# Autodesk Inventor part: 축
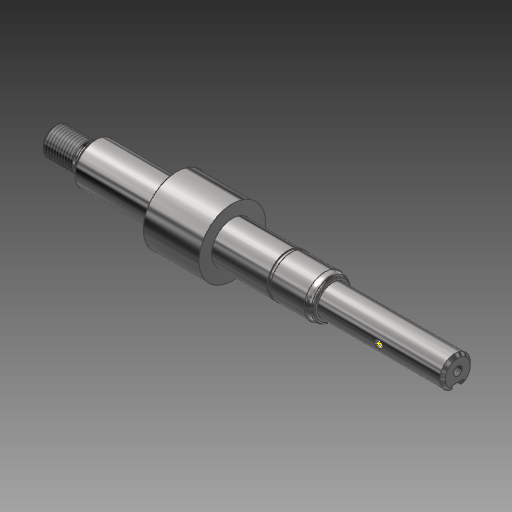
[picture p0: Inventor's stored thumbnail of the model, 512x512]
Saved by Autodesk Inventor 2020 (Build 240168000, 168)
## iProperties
Created: 2016-08
Part Number: 축
Material: 강철, 탄소
Document SubType Name: Modeling
Designer: mduedu
Density: 7.87 g/cm^3
Appearance: 반광택
Author: mduedu
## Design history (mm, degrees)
sketch "스케치1"
  geometry: L1 (-72.5, 0)-(72.5, 0); L2 (-72.5, 0)-(-72.5, 5); L3 (-72.5, 5)-(-58.5, 5); L4 (-58.5, 5)-(-58.5, 7.5); L5 (-58.5, 7.5)-(25.855, 7.5); L6 (27.5, 6.55)-(27.5, 5.5); L7 (27.5, 5.5)-(72.5, 5.5); L8 (72.5, 5.5)-(72.5, 0); L9 (27.5, 6.55)-(25.855, 7.5); 2 further points
  constraints: 18 end point, 5 parallel, 2 perpendicular, 1 coincident, 1 horizontal, 1 midpoint
  dimensions: "d0" = 145 distance of L1.start L1.end; "d2" = 14 distance of L2.end L3.end; "d4" = 10 diameter of L3 L1; "d5" = 15 diameter of L5 L1; "d6" = 11 diameter of L7 L1; "d63" = 45 distance between parallel lines of L6 L8; "d64" = 30 deg angle of L5 L9; "d65" = 13.1 diameter of L6.start L1
revolve "회전1" sketch "스케치1" stored, may be unused: angle "d7" = 90 deg
sketch "스케치2"
  geometry: L1 (-58.5, -5)-(-58.5, 5) reference; L2 (72.5, -5.5)-(72.5, 5.5) reference; L3 (-58.5, 0)-(72.5, 0); L4 (-60.5, 4.5)-(-60.5, 5); L5 (-60.5, 5)-(-58.5, 5); L6 (-58.5, 5)-(-58.5, 4.5); L7 (-60.5, 4.5)-(-58.5, 4.5); 1 further point
  constraints: 10 end point, 2 midpoint, 1 parallel, 1 perpendicular, 1 point on line
  dimensions: "d8" = 2 distance of L4.end L5.end; "d10" = 10 diameter of L5 L3; "d11" = 9 diameter of L7 L3
revolve "회전2" sketch "스케치2" stored, may be unused: angle "d12" = 90 deg
node "작업 평면1"
sketch "스케치3"
  geometry: C1 r 12 at (0, 0); 1 further point
  constraints: 1 centre point, 1 coincident
  dimensions: "d15" = 24 diameter of C1
extrude "돌출1" join sketch "스케치3" distance "d16" = 20; taper "d17" = 0 deg
sketch "스케치5"
  geometry: L1 (-72.5, -5)-(-72.5, 5) reference; L2 (72.5, -5.5)-(72.5, 5.5) reference; L3 (-72.5, 0)-(72.5, 0); L4 (-8.5, 7.5)-(25.855, 7.5) reference; L5 (12.65, 7.5)-(11.5, 7.5); L6 (11.5, 7.5)-(11.5, 7.15); L7 (11.5, 7.15)-(12.65, 7.15); L8 (12.65, 7.15)-(12.65, 7.5); L9 (-8.5, -12)-(-8.5, 12) reference; 1 further point
  constraints: 10 end point, 2 midpoint, 2 parallel, 1 horizontal, 1 perpendicular, 1 point on line
  dimensions: "d20" = 1.15 distance between parallel lines of L8 L6; "d21" = 14.3 diameter of L7 L3; "d82" = 20 distance between parallel lines of L9 L6
revolve "회전3" sketch "스케치5" stored, may be unused: angle "d22" = 90 deg
node "작업 평면3"
sketch "스케치6"
  geometry: L1 (-6.5, 2)-(-22.5, 2); L2 (-22.5, 2)-(-22.5, -2); L3 (-22.5, -2)-(-6.5, -2); L4 (-22.5, 5.5)-(-22.5, -5.5) reference; A1 r 2 centre (-6.5, 0) between (-6.5, -2) and (-6.5, 2); 2 further points
  constraints: 6 end point, 2 midpoint, 2 point on circle, 2 tangent, 1 centre point, 1 horizontal, 1 horizontal alignment, 1 parallel, 1 perpendicular
  dimensions: "d23" = 4 distance between parallel lines of L3 L1; "d62" = 18 dimension on A1 L2
extrude "돌출2" cut sketch "스케치6" distance "d25" = 2.5; taper "d26" = 0 deg
feature "스레드1" dims "d27" = 10, "d28" = 0
chamfer "모따기5" distance "d41" = 0.5; stored, may be unused: second distance "d42" = 2, angle "d43" = 45 deg
chamfer "모따기7" distance "d47" = 1; stored, may be unused: second distance "d48" = 2, angle "d49" = 45 deg
chamfer "모따기8" distance "d50" = 1; stored, may be unused: second distance "d51" = 2, angle "d52" = 45 deg
sketch "스케치8"
  geometry: 1 further point
hole "구멍1" sketch "스케치8" at (2, 3.5) diameter "d53" = 3.242; stored, may be unused: countersink angle "d57" = 90 deg, drill point angle "d59" = 120 deg; dims "d54" = 10, "d55" = 4, "d56" = 2, "d58" = 12
fillet "모깎기1" dims "d66" = 4, "d67" = 0.5
sketch "스케치10"
  geometry: L1 (-27.5, 5.5)-(-71.5, 5.5) reference; L2 (-51, 5.5)-(-49.5, 4); L3 (-49.5, 4)-(-49.5, 5.5); L4 (-72.5, -4.5)-(-72.5, 4.5) reference; 3 further points
  constraints: 4 end point, 1 midpoint, 1 perpendicular, 1 point on line
  dimensions: "d77" = 45 deg angle of L2 L3; "d78" = 3 diameter of L2.start L3; "d80" = 23 distance between parallel lines of L4 L3
revolve "회전4" sketch "스케치10" stored, may be unused: angle "d81" = 90 deg
node "작업점1"
node "솔리드1"
other parameters: "d13" = -44
